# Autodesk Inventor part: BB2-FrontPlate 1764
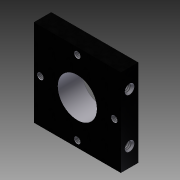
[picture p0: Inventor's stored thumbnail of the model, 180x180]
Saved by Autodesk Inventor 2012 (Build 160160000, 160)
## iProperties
Company: FirstCadLibrary
Shininess: 64.0
Length Units: 11269
Angle Units: 11279
Time Units: 11290
Mass Units: 11283
Length Display Precision: 3
Angle Display Precision: 2
Compacted: True
Part Number: BB2-FrontPlate 1764
Document SubType Name: Modeling
Created: 2007-01
Designer: Ed Sparks
Material: Aluminum-6061-AHC
Catalog Web Link: www.banebots.com
Vendor: BaneBots
Mass: 132.736 g
Surface Area: 141.952 cm^2
Volume: 48.98 cm^3
Density: 2.71 g/cm^3
Density: 0.0
Volumn: 0.0
Area: 0.0
PropertySet Name: Model Information
Control State: 0
Master: False
Checked Out: False
Author: Ed Sparks
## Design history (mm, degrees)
sketch "Sketch1"
  geometry: L1 (-31.75, 31.75)-(31.75, 31.75); L2 (31.75, 31.75)-(31.75, -31.75); L3 (31.75, -31.75)-(-31.75, -31.75); L4 (-31.75, -31.75)-(-31.75, 31.75); L5 (0, 0)-(0, 31.75); L6 (0, 0)-(0, -31.75); L7 (0, 0)-(31.75, 0); L8 (0, 0)-(-31.75, 0)
  constraints: 16 end point, 4 midpoint, 2 collinear, 2 parallel, 1 horizontal, 1 perpendicular, 1 other
  dimensions: "d0" = 63.5 distance of L1.end L2.end; "d1" = 63.5 distance of L1.start L1.end
extrude "Extrusion1" new body sketch "Sketch1" stored distance "d2" = 12.7; taper "d3" = 0 deg
sketch "Sketch6"
  geometry: C1 r 25 at (0, 0)
  constraints: 1 centre point
  dimensions: "d13" = 50 diameter of C1
extrude "Extrusion4" join sketch "Sketch6" distance "d14" = 6; taper "d15" = 0 deg
sketch "Sketch8"
  geometry: C1 r 25 at (0, 0) reference; 1 further point
  constraints: 1 coincident
hole "Hole2" sketch "Sketch8" at (0, 0) diameter "d28" = 28.575; stored, may be unused: countersink angle "d32" = 82 deg, drill point angle "d34" = 118 deg; dims "d29" = 6, "d30" = 6.3, "d31" = 10.3, "d33" = 8
chamfer "Chamfer1" distance "d35" = 1; stored, may be unused: second distance "d36" = 2, angle "d72" = 45 deg
sketch "Sketch9"
  geometry: L1 (63.5, 0)-(0, 0) reference; L2 (0, 0)-(0, -12.7) reference; L3 (0, -12.7)-(63.5, -12.7) reference; L4 (63.5, 0)-(63.5, -12.7) reference; L5 (0, -6.35)-(63.5, -6.35); L6 (31.75, 0)-(31.75, -12.7); 1 further point
  constraints: 4 end point, 4 midpoint, 1 point on line
  dimensions: "d37" = 18 distance from line of point (13.75, -6.35) L6
hole "Hole3" sketch "Sketch9" at (13.75, -6.35) diameter "d38" = 4.978; stored, may be unused: countersink angle "d42" = 82 deg, drill point angle "d44" = 118 deg; dims "d39" = 12, "d40" = 6.3, "d41" = 10.3, "d43" = 13.7
mirror "Mirror1"
mirror "Mirror2"
chamfer "Chamfer2" distance "d45" = 1; stored, may be unused: second distance "d46" = 2, angle "d73" = 45 deg
workplane "Work Plane1"
sketch "Sketch10"
  geometry: L1 (-31.75, -6.35)-(31.75, -6.35) reference; L2 (0, -6.35)-(0, -22.916); 1 further point
  constraints: 2 end point, 1 midpoint, 1 perpendicular, 1 point on line
  dimensions: "d48" = 3.5 distance from line of point (0, -9.85) L1
hole "Hole4" sketch "Sketch10" at (0, -9.85) diameter "d49" = 2.459; stored, may be unused: countersink angle "d53" = 82 deg, drill point angle "d55" = 118 deg; dims "d50" = 6, "d51" = 6.3, "d52" = 10.3, "d54" = 7.5
pattern_circular "Circular Pattern2" dims angle "d58" = 360 deg
sketch "Sketch11"
  geometry: L1 (31.75, -31.75)-(-31.75, -31.75) reference; L2 (0, 0)-(36.641, 0); C1 r 14.287 at (0, 0) reference; 1 further point
  constraints: 2 end point, 1 parallel, 1 point on line
  dimensions: "d59" = 26.9875 distance of point (26.988, 0) L2.start
hole "Hole5" sketch "Sketch11" at (26.988, 0) diameter "d60" = 4.134; stored, may be unused: countersink angle "d64" = 82 deg, drill point angle "d66" = 118 deg; dims "d61" = 6, "d62" = 4, "d63" = 2, "d65" = 8
pattern_circular "Circular Pattern3" dims angle "d69" = 360 deg
chamfer "Chamfer3" distance "d70" = 0.25; stored, may be unused: second distance "d71" = 2, angle "d74" = 45 deg
body "Solid1"
other parameters: "d47" = 25
